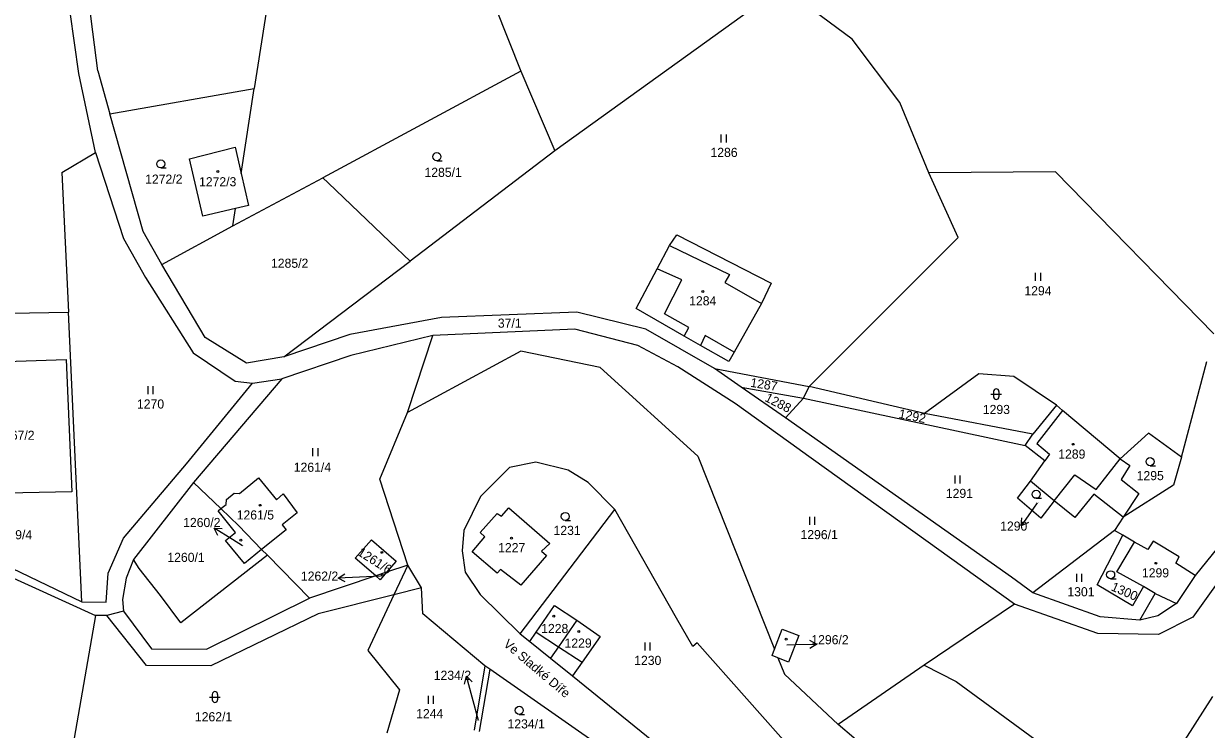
# Model space of a CAD drawing. Extents: x -670359 to -668019, y -978807 to -976674.
# Drawn here: x -670066.9 to -669846.5, y -978074.2 to -977942.9 of the extents above; entities that cross this region are included whole.
import ezdxf

# ---------------------------------------------------------------- set-up
doc = ezdxf.new("R2010")
doc.units = 0
for name, color, linetype in [('Hranice parcel', 7, 'Continuous'), ('Parcelní čísla', 7, 'Continuous'), ('Pop  PČ popisy', 7, 'Continuous'), ('Vnitřní kresba', 7, 'Continuous'), ('Značky budov', 7, 'Continuous'), ('Značky kultur', 7, 'Continuous')]:
    doc.layers.add(name, color=color, linetype=linetype)

msp = doc.modelspace()

# ---------------------------------------------------------------- linework, layer by layer
at = {"layer": 'Hranice parcel'}
for points in [[(-670053.06, -977951.64), (-670057.82, -977914.27)], [(-669986.12, -977921.83), (-669974.21, -977951.73)], [(-670020.22, -977931.15), (-670023.9, -977954.91)], [(-669912.5, -977945.77), (-669928, -977934.27)], [(-670056.57, -977952.14), (-670059, -977934.95)], [(-669929.41, -977938.84), (-669967.89, -977966.56)], [(-669903.64, -977957.54), (-669912.5, -977945.77)], [(-670053.5, -977966.83), (-670056.57, -977952.14)], [(-670053.06, -977951.64), (-670050.8, -977959.63)], [(-669974.21, -977951.73), (-670011.15, -977971.53)], [(-669974.21, -977951.73), (-669967.89, -977966.56)], [(-670050.8, -977959.63), (-670023.9, -977954.91)], [(-670026.36, -977970.75), (-670023.9, -977954.91)], [(-669898.21, -977970.61), (-669903.64, -977957.54)], [(-670044.58, -977981.56), (-670050.8, -977959.63)], [(-670059.75, -977970.54), (-670053.5, -977966.83)], [(-670053.5, -977966.83), (-670048.25, -977982.86)], [(-670035.99, -977968.05), (-670027.48, -977965.87)], [(-670027.48, -977965.87), (-670026.36, -977970.75)], [(-669967.89, -977966.56), (-669994.86, -977987.04)], [(-670033.51, -977978.72), (-670035.99, -977968.05)], [(-670059.75, -977970.54), (-670058.53, -977996.56)], [(-670027.87, -977980.5), (-670011.15, -977971.53)], [(-670026.36, -977970.75), (-670024.98, -977976.72)], [(-670011.15, -977971.53), (-670010.16, -977972.48)], [(-669874.62, -977970.47), (-669898.21, -977970.61)], [(-669892.79, -977982.65), (-669898.21, -977970.61)], [(-669845.11, -978000.59), (-669874.62, -977970.47)], [(-670010.16, -977972.48), (-669998.63, -977983.45)], [(-670027.37, -977977.28), (-670033.51, -977978.72)], [(-670027.87, -977980.5), (-670027.37, -977977.28)], [(-670024.98, -977976.72), (-670027.37, -977977.28)], [(-670041.11, -977987.69), (-670027.87, -977980.5)], [(-670048.25, -977982.86), (-670044.13, -977990.1)], [(-670041.11, -977987.69), (-670044.58, -977981.56)], [(-669946.52, -977984.17), (-669945.17, -977982.16)], [(-669945.17, -977982.16), (-669927.61, -977991.17)], [(-669920.55, -978010.38), (-669892.79, -977982.65)], [(-669998.63, -977983.45), (-669994.86, -977987.04)], [(-669948.82, -977988.5), (-669946.52, -977984.17)], [(-670018.38, -978004.9), (-669994.86, -977987.04)], [(-670033.04, -978001.31), (-670041.11, -977987.69)], [(-669952.75, -977995.9), (-669948.82, -977988.5)], [(-670044.13, -977990.1), (-670035.26, -978004.12)], [(-669927.61, -977991.17), (-669929.43, -977994.93)], [(-669943.79, -978001.01), (-669952.75, -977995.9)], [(-669929.43, -977994.93), (-669934.5, -978004)], [(-670087.67, -977997.06), (-670058.53, -977996.56)], [(-670056, -978050.5), (-670058.53, -977996.56)], [(-669988.99, -977997.53), (-670006.09, -978000.75)], [(-669963.81, -977996.58), (-669988.99, -977997.53)], [(-669950.92, -977999.7), (-669963.81, -977996.58)], [(-670006.09, -978000.75), (-670018.38, -978004.9)], [(-669964.19, -977999.7), (-669990.66, -978000.89)], [(-669952.42, -978002.74), (-669964.19, -977999.7)], [(-669938.16, -978007.05), (-669950.92, -977999.7)], [(-670025.34, -978006.06), (-670033.04, -978001.31)], [(-669990.66, -978000.89), (-670005.91, -978004.66)], [(-669995.38, -978015.23), (-669990.66, -978000.89)], [(-669944.96, -978006.77), (-669952.42, -978002.74)], [(-669940.74, -978002.75), (-669943.79, -978001.01)], [(-669935.48, -978005.76), (-669940.74, -978002.75)], [(-670035.26, -978004.12), (-670027.48, -978009.42)], [(-670018.38, -978004.9), (-670025.34, -978006.06)], [(-670005.91, -978004.66), (-670018.76, -978008.97)], [(-669974.25, -978003.83), (-669995.38, -978015.23)], [(-669959.43, -978006.86), (-669974.25, -978003.83)], [(-669934.5, -978004), (-669935.48, -978005.76)], [(-670083.31, -978006.16), (-670058.93, -978005.38)], [(-670058.93, -978005.38), (-670057.91, -978029.98)], [(-669941.27, -978023.37), (-669959.43, -978006.86)], [(-669934.29, -978013.58), (-669944.96, -978006.77)], [(-669933.18, -978010.54), (-669938.16, -978007.05)], [(-669938.16, -978007.05), (-669920.55, -978010.38)], [(-669851.14, -978023.56), (-669846.46, -978005.72)], [(-670018.76, -978008.97), (-670035.21, -978028.25)], [(-670027.48, -978009.42), (-670024.2, -978009.8)], [(-670024.2, -978009.8), (-670018.76, -978008.97)], [(-669888.89, -978008.04), (-669899.01, -978015.45)], [(-669882.41, -978008.56), (-669888.89, -978008.04)], [(-669874.47, -978013.87), (-669882.41, -978008.56)], [(-670036.51, -978024.82), (-670024.2, -978009.8)], [(-669924.92, -978016.24), (-669933.18, -978010.54)], [(-669933.18, -978010.54), (-669921.58, -978012.55)], [(-669921.58, -978012.55), (-669920.55, -978010.38)], [(-669899.01, -978015.45), (-669920.55, -978010.38)], [(-669922.37, -978022.14), (-669934.29, -978013.58)], [(-669924.92, -978016.24), (-669921.58, -978012.55)], [(-669921.58, -978012.55), (-669880.27, -978021.41)], [(-669874.47, -978013.87), (-669878.84, -978019.25)], [(-669873.34, -978014.9), (-669874.47, -978013.87)], [(-670000.51, -978027.64), (-669995.38, -978015.23)], [(-669878.84, -978019.25), (-669899.01, -978015.45)], [(-669862.58, -978023.86), (-669873.34, -978014.9)], [(-669882.85, -978045.88), (-669924.92, -978016.24)], [(-669880.27, -978021.41), (-669878.84, -978019.25)], [(-669857.33, -978019.12), (-669862.58, -978023.86)], [(-669851.14, -978023.56), (-669857.33, -978019.12)], [(-669922.15, -978022.29), (-669922.37, -978022.14)], [(-669882.27, -978050.91), (-669922.15, -978022.29)], [(-669876.65, -978024.27), (-669880.27, -978021.41)], [(-670048.27, -978038.64), (-670036.51, -978024.82)], [(-669971.42, -978024.51), (-669976.37, -978025.5)], [(-669965.41, -978026), (-669971.42, -978024.51)], [(-669941.27, -978023.37), (-669926.98, -978059.31)], [(-669879.27, -978028.04), (-669876.65, -978024.27)], [(-669862.58, -978023.86), (-669860.81, -978025.13)], [(-669851.14, -978023.56), (-669852.64, -978028.76)], [(-669976.37, -978025.5), (-669981.78, -978030.89)], [(-669961.72, -978028.29), (-669965.41, -978026)], [(-669860.81, -978025.13), (-669862.4, -978027.7)], [(-670035.21, -978028.25), (-670046.41, -978042.62)], [(-670030.13, -978033.12), (-670035.21, -978028.25)], [(-670030.13, -978033.12), (-670029.16, -978032.34), (-670029.07, -978031.43), (-670027.62, -978030.26), (-670026.64, -978030.3), (-670023.09, -978027.43), (-670019.78, -978031.52), (-670018.53, -978030.41), (-670015.91, -978033.93), (-670018.67, -978036.17), (-670017.94, -978037.06), (-670022.54, -978040.77)], [(-669995.3, -978043.67), (-670000.51, -978027.64)], [(-669956.73, -978033.3), (-669961.72, -978028.29)], [(-669881.73, -978031.17), (-669879.27, -978028.04)], [(-669874.85, -978031.69), (-669879.27, -978028.04)], [(-669862.4, -978027.7), (-669859.11, -978030.32)], [(-669852.64, -978028.76), (-669862.04, -978034.73)], [(-670057.91, -978029.98), (-670082.22, -978030.53)], [(-669981.78, -978030.89), (-669984.86, -978037.22)], [(-669877.39, -978034.9), (-669881.73, -978031.17)], [(-669867.5, -978030.45), (-669871, -978034.78)], [(-669862.04, -978034.73), (-669867.5, -978030.45)], [(-669859.11, -978030.32), (-669862.04, -978034.73)], [(-669837.27, -978031.54), (-669848.63, -978045.6)], [(-670022.54, -978040.77), (-670025.74, -978043.36), (-670029.23, -978039.04), (-670027.4, -978037.57), (-670030.65, -978033.55), (-670030.13, -978033.12)], [(-670026.77, -978036.35), (-670030.13, -978033.12)], [(-669977.84, -978034.54), (-669976.49, -978033.01)], [(-669976.49, -978033.01), (-669968.85, -978039.6)], [(-669974.36, -978056.42), (-669956.73, -978033.3)], [(-669945.24, -978053.55), (-669956.73, -978033.3)], [(-669874.85, -978031.69), (-669877.39, -978034.9)], [(-669871, -978034.78), (-669874.85, -978031.69)], [(-669834.38, -978032.89), (-669849.06, -978053.35)], [(-669981.82, -978037.6), (-669978.64, -978034.07)], [(-669978.64, -978034.07), (-669977.84, -978034.54)], [(-669862.04, -978034.73), (-669863.64, -978037.18)], [(-670083.87, -978037.17), (-670056, -978050.5)], [(-670022.54, -978040.77), (-670026.77, -978036.35)], [(-669984.86, -978037.22), (-669985.16, -978040.98)], [(-669980.94, -978038.39), (-669981.82, -978037.6)], [(-669863.64, -978037.18), (-669878.84, -978048.81)], [(-669866.85, -978047.3), (-669862.1, -978038.09)], [(-669862.1, -978038.09), (-669863.64, -978037.18)], [(-669859.94, -978039.35), (-669862.1, -978038.09)], [(-670083.53, -978039.41), (-670053.47, -978053.05)], [(-670051.11, -978045.13), (-670048.27, -978038.64)], [(-670005.07, -978042.39), (-670002.08, -978038.94)], [(-670002.08, -978038.94), (-669997.46, -978042.91)], [(-669983.32, -978041.21), (-669980.94, -978038.39)], [(-669968.85, -978039.6), (-669970.37, -978041.05)], [(-669863.19, -978044.88), (-669859.94, -978039.35)], [(-669857.45, -978040.77), (-669859.94, -978039.35)], [(-669856.42, -978039.17), (-669857.45, -978040.77)], [(-669851.6, -978042.1), (-669856.42, -978039.17)], [(-670046.41, -978042.62), (-670047.75, -978046.07)], [(-670045.36, -978044.29), (-670046.41, -978042.62)], [(-670021.46, -978041.83), (-670037.55, -978054.4)], [(-670021.46, -978041.83), (-670022.54, -978040.77)], [(-670013.58, -978049.78), (-670021.46, -978041.83)], [(-670001.27, -978045.67), (-670005.07, -978042.39)], [(-669985.16, -978040.98), (-669984.58, -978044.97)], [(-669978.66, -978045.17), (-669983.32, -978041.21)], [(-669969.48, -978041.84), (-669974.25, -978047.39)], [(-669970.37, -978041.05), (-669969.48, -978041.84)], [(-669852.24, -978043.3), (-669851.6, -978042.1)], [(-670041.34, -978049.3), (-670045.36, -978044.29)], [(-669997.46, -978042.91), (-669999.26, -978044.99)], [(-669995.3, -978043.67), (-669999.26, -978044.99)], [(-669995.3, -978043.67), (-669997.88, -978049.19)], [(-669992.72, -978047.89), (-669995.3, -978043.67)], [(-669978.03, -978044.45), (-669978.66, -978045.17)], [(-669974.25, -978047.39), (-669978.03, -978044.45)], [(-669848.63, -978045.6), (-669852.24, -978043.3)], [(-670051.49, -978050.56), (-670051.11, -978045.13)], [(-670047.75, -978046.07), (-670048.45, -978050.07)], [(-670001.27, -978045.67), (-670013.58, -978049.78)], [(-669999.26, -978044.99), (-670001.27, -978045.67)], [(-670000.45, -978046.37), (-670001.27, -978045.67)], [(-669999.26, -978044.99), (-670000.45, -978046.37)], [(-669984.58, -978044.97), (-669981.84, -978049.11)], [(-669878.84, -978048.81), (-669882.85, -978045.88)], [(-669858.21, -978047.65), (-669863.19, -978044.88)], [(-669848.63, -978045.6), (-669852.12, -978050.81)], [(-669997.88, -978049.19), (-670002.72, -978059.52)], [(-669992.48, -978052.73), (-669992.72, -978047.89)], [(-669981.84, -978049.11), (-669974.36, -978056.42)], [(-669866.34, -978053.29), (-669878.84, -978048.81)], [(-669860.27, -978051.26), (-669866.85, -978047.3)], [(-669858.21, -978047.65), (-669860.27, -978051.26)], [(-669858.9, -978053.89), (-669856.05, -978048.92)], [(-669856.05, -978048.92), (-669858.21, -978047.65)], [(-670056, -978050.5), (-670051.49, -978050.56)], [(-670048.45, -978050.07), (-670048.28, -978052.22)], [(-670037.55, -978054.4), (-670041.34, -978049.3)], [(-669971.4, -978056.16), (-669967.99, -978051.18)], [(-669967.99, -978051.18), (-669963.82, -978053.88)], [(-669882.27, -978050.91), (-669899.08, -978062.28)], [(-669866.72, -978056.41), (-669882.27, -978050.91)], [(-669852.12, -978050.81), (-669855.54, -978053.07)], [(-670053.47, -978053.05), (-670058.45, -978081.6)], [(-670051.39, -978053.04), (-670053.47, -978053.05)], [(-670048.28, -978052.22), (-670051.39, -978053.04)], [(-669980.96, -978062.4), (-669992.48, -978052.73)], [(-669942.19, -978058.82), (-669945.24, -978053.55)], [(-669858.9, -978053.89), (-669866.34, -978053.29)], [(-669855.54, -978053.07), (-669858.9, -978053.89)], [(-669849.06, -978053.35), (-669855.44, -978056.59)], [(-669963.82, -978053.88), (-669967.23, -978058.85)], [(-669963.82, -978053.88), (-669959.48, -978056.97)], [(-669926.98, -978059.31), (-669925.55, -978055.57)], [(-669925.55, -978055.57), (-669922.46, -978056.76)], [(-669974.36, -978056.42), (-669972.57, -978057.86)], [(-669972.57, -978057.86), (-669971.4, -978056.16)], [(-669972.57, -978057.86), (-669968.7, -978060.99)], [(-669959.48, -978056.97), (-669962.82, -978061.7)], [(-669922.46, -978056.76), (-669924.36, -978061.71)], [(-669855.44, -978056.59), (-669866.72, -978056.41)], [(-670002.72, -978059.52), (-669996.86, -978066.86)], [(-669967.23, -978058.85), (-669968.7, -978060.99)], [(-669941.37, -978058.13), (-669942.19, -978058.82)], [(-669932.15, -978068.55), (-669941.37, -978058.13)], [(-669927.43, -978060.47), (-669926.98, -978059.31)], [(-669980.96, -978062.4), (-669982.91, -978074.36)], [(-669980.03, -978063.05), (-669980.96, -978062.4)], [(-669968.7, -978060.99), (-669964.64, -978064.28)], [(-669962.82, -978061.7), (-669964.64, -978064.28)], [(-669926.35, -978060.91), (-669927.43, -978060.47)], [(-669926.35, -978060.91), (-669925.14, -978063.95)], [(-669924.36, -978061.71), (-669926.35, -978060.91)], [(-669899.08, -978062.28), (-669915.09, -978073.32)], [(-669899.08, -978062.28), (-669893.12, -978065.33)], [(-669980.03, -978063.05), (-669981.98, -978074.61)], [(-669951.97, -978082.63), (-669980.03, -978063.05)], [(-669964.64, -978064.28), (-669935.73, -978087.67)], [(-669915.09, -978073.32), (-669925.14, -978063.95)], [(-669996.86, -978066.86), (-669999.21, -978074.92)], [(-669893.12, -978065.33), (-669864.05, -978086.6)], [(-669922.9, -978078.96), (-669932.15, -978068.55)], [(-669845.36, -978068.08), (-669851.96, -978078.41)], [(-669903.47, -978083.25), (-669915.09, -978073.32)]]:
    msp.add_lwpolyline(points, dxfattribs=at)
at = {"layer": 'Parcelní čísla'}
for p, q in [((-669878.05, -978032.08), (-669878.75, -978033.08)), ((-669879.68, -978035.72), (-669881.04, -978036.36)), ((-670030.66, -978038.11), (-670031.37, -978036.79)), ((-670026.07, -978040.08), (-670027.97, -978038.9)), ((-670006.94, -978046.78), (-670008.28, -978046.1)), ((-670000.44, -978045.71), (-670004.28, -978045.9)), ((-669920.44, -978057.65), (-669919.12, -978058.37)), ((-669924.7, -978058.48), (-669923.12, -978058.45)), ((-669984.76, -978065.8), (-669984.38, -978064.35)), ((-669982.15, -978072.58), (-669983.33, -978068.21))]:
    msp.add_line(p, q, dxfattribs=at)
for points in [[(-669878.75, -978033.08), (-669881.04, -978036.36), (-669880.91, -978034.87)], [(-670027.97, -978038.9), (-670031.37, -978036.79), (-670029.87, -978036.84)], [(-670004.28, -978045.9), (-670008.28, -978046.1), (-670007.01, -978045.28)], [(-669923.12, -978058.45), (-669919.12, -978058.37), (-669920.41, -978059.15)], [(-669983.33, -978068.21), (-669984.38, -978064.35), (-669983.31, -978065.41)]]:
    msp.add_lwpolyline(points, dxfattribs=at)
at = {"layer": 'Vnitřní kresba'}
for points in [[(-669946.52, -977984.17), (-669935.38, -977989.54)], [(-669944.25, -977990.55), (-669948.82, -977988.5)], [(-669935.38, -977989.54), (-669936.25, -977991.06)], [(-669947.49, -977996.88), (-669944.25, -977990.55)], [(-669936.25, -977991.06), (-669929.43, -977994.93)], [(-669942.92, -977999.41), (-669947.49, -977996.88)], [(-669943.79, -978001.01), (-669942.92, -977999.41)], [(-669939.87, -978000.91), (-669940.74, -978002.75)], [(-669934.5, -978004), (-669939.87, -978000.91)], [(-669873.34, -978014.9), (-669878.11, -978021)], [(-669878.11, -978021), (-669875.78, -978022.98)], [(-669875.78, -978022.98), (-669876.65, -978024.27)], [(-669867.03, -978029.56), (-669862.58, -978023.86)], [(-669874.85, -978031.69), (-669871.04, -978026.87)], [(-669871.04, -978026.87), (-669867.03, -978029.56)], [(-669997.88, -978049.19), (-670011.97, -978052.72)], [(-669992.72, -978047.89), (-669997.88, -978049.19)], [(-669856.05, -978048.92), (-669852.12, -978050.81)], [(-670032.8, -978059.32), (-670013.58, -978049.78)], [(-670043.98, -978062.35), (-670051.39, -978053.04)], [(-670048.28, -978052.22), (-670043.04, -978059.22)], [(-670011.97, -978052.72), (-670031.99, -978062.43)], [(-669971.4, -978056.16), (-669967.23, -978058.85)], [(-670043.04, -978059.22), (-670032.8, -978059.32)], [(-669967.23, -978058.85), (-669962.82, -978061.7)], [(-670031.99, -978062.43), (-670043.98, -978062.35)]]:
    msp.add_lwpolyline(points, dxfattribs=at)
at = {"layer": 'Značky budov'}
for centre in [(-670030.68, -977970.37), (-669940.34, -977992.7), (-669871.34, -978021.16), (-670022.8, -978032.52), (-669975.97, -978038.65), (-669855.91, -978043.31), (-670000.05, -978045.52), (-669968.12, -978053.16), (-669963.46, -978056.02), (-669924.79, -978057.42)]:
    msp.add_circle(centre, 0.175, dxfattribs=at)
at = {"layer": 'Značky kultur'}
for p, q in [((-669936.95, -977963.47), (-669936.95, -977964.97)), ((-669935.95, -977964.97), (-669935.95, -977963.47)), ((-670041.31, -977969.72), (-670040.31, -977969.72)), ((-669989.88, -977968.37), (-669988.88, -977968.37)), ((-669878.39, -977989.23), (-669878.39, -977990.73)), ((-669877.39, -977990.73), (-669877.39, -977989.23)), ((-670043.75, -978010.31), (-670043.75, -978011.81)), ((-670042.75, -978011.81), (-670042.75, -978010.31)), ((-669886.17, -978011.33), (-669886.17, -978012.33)), ((-669885.17, -978011.33), (-669885.17, -978012.33)), ((-669886.67, -978011.83), (-669884.67, -978011.83)), ((-670013.02, -978021.89), (-670013.02, -978023.39)), ((-670012.02, -978023.39), (-670012.02, -978021.89)), ((-669893.38, -978026.95), (-669893.38, -978028.45)), ((-669892.38, -978028.45), (-669892.38, -978026.95)), ((-669857.01, -978025.14), (-669856.01, -978025.14)), ((-669878.24, -978031.22), (-669877.24, -978031.22)), ((-669965.97, -978035.34), (-669964.97, -978035.34)), ((-669920.48, -978034.66), (-669920.48, -978036.16)), ((-669919.48, -978036.16), (-669919.48, -978034.66)), ((-669870.74, -978045.26), (-669870.74, -978046.76)), ((-669869.74, -978046.76), (-669869.74, -978045.26)), ((-669864.36, -978046.19), (-669863.36, -978046.19)), ((-669951.12, -978058.04), (-669951.12, -978059.54)), ((-669950.12, -978059.54), (-669950.12, -978058.04)), ((-670032.23, -978068.21), (-670030.23, -978068.21)), ((-670031.73, -978067.71), (-670031.73, -978068.71)), ((-670030.73, -978067.71), (-670030.73, -978068.71)), ((-669991.52, -978068), (-669991.52, -978069.5)), ((-669990.52, -978069.5), (-669990.52, -978068)), ((-669974.53, -978071.44), (-669973.53, -978071.44))]:
    msp.add_line(p, q, dxfattribs=at)
for centre, radius in [((-669989.88, -977967.62), 0.75), ((-670041.31, -977968.97), 0.75), ((-670030.68, -977970.37), 0.175), ((-669940.34, -977992.7), 0.175), ((-669871.34, -978021.16), 0.175), ((-669857.01, -978024.39), 0.75), ((-669878.24, -978030.47), 0.75), ((-670022.8, -978032.52), 0.175), ((-669965.97, -978034.59), 0.75), ((-670026.4, -978039.02), 0.175), ((-669975.97, -978038.65), 0.175), ((-670000.11, -978041.28), 0.175), ((-669864.36, -978045.44), 0.75), ((-669855.91, -978043.31), 0.175), ((-670000.05, -978045.52), 0.175), ((-669968.12, -978053.16), 0.175), ((-669963.46, -978056.02), 0.175), ((-669924.79, -978057.42), 0.175), ((-669974.53, -978070.69), 0.75)]:
    msp.add_circle(centre, radius, dxfattribs=at)
for centre, start, end in [((-669885.67, -978011.33), 0, 180), ((-669885.67, -978012.33), 180, 0), ((-670031.23, -978067.71), 0, 180), ((-670031.23, -978068.71), 180, 0)]:
    msp.add_arc(centre, 0.5, start, end, dxfattribs=at)

# ---------------------------------------------------------------- texts
at = {"layer": 'Parcelní čísla'}
for s, height, p in [('1286', 1.7, (-669938.91, -977967.67)), ('1285/1', 1.7, (-669992.19, -977971.38)), ('1272/2', 1.7, (-670044.23, -977972.65)), ('1272/3', 1.7, (-670034.19, -977973.14)), ('1285/2', 1.7, (-670020.78, -977988.3)), ('1294', 1.7, (-669880.43, -977993.43)), ('1284', 1.7, (-669942.88, -977995.3)), ('37/1', 1.7, (-669978.52, -977999.46)), ('1270', 1.7, (-670045.75, -978014.51)), ('1293', 1.7, (-669888.17, -978015.53)), ('1267/2', 1.7, (-670071.78, -978020.33)), ('1289', 1.7, (-669874.12, -978023.83)), ('1261/4', 1.7, (-670016.54, -978026.28)), ('1295', 1.7, (-669859.51, -978027.84)), ('1291', 1.7, (-669895.06, -978031.15)), ('1261/5', 1.7, (-670027.17, -978035.16)), ('1290', 0.1, (-669878.05, -978032.08)), ('1260/2', 1.7, (-670037.15, -978036.57)), ('1290', 1.7, (-669884.94, -978037.24)), ('1269/4', 1.7, (-670072.23, -978038.85)), ('1231', 1.7, (-669968.15, -978038.04)), ('1296/1', 1.7, (-669922.14, -978038.82)), ('1260/2', 0.1, (-670026.31, -978040.08)), ('1227', 1.7, (-669978.47, -978041.25)), ('1260/1', 1.7, (-670040.09, -978043.06)), ('1262/2', 1.7, (-670015.21, -978046.55)), ('1299', 1.7, (-669858.53, -978045.94)), ('1262/2', 0.1, (-670000.68, -978045.71)), ('1301', 1.7, (-669872.42, -978049.46)), ('1228', 1.7, (-669970.45, -978056.3)), ('1229', 1.7, (-669966.1, -978059.02)), ('1296/2', 1.7, (-669920.12, -978058.39)), ('1296/2', 0.1, (-669924.7, -978058.48)), ('1230', 1.7, (-669953.12, -978062.24)), ('1234/2', 1.7, (-669990.46, -978065.01)), ('1262/1', 1.7, (-670034.96, -978072.73)), ('1244', 1.7, (-669993.74, -978072.15)), ('1234/2', 0.1, (-669982.39, -978072.58)), ('1234/1', 1.7, (-669976.72, -978074.06))]:
    msp.add_text(s, height=height, dxfattribs=at).set_placement(p)
for s, rotation, p in [('1287', 350.9747, (-669931.56, -978010.45)), ('1288', 332.796, (-669928.93, -978013.04)), ('1292', 348.918, (-669903.94, -978016.25)), ('1261/6', 327.5321, (-670004.81, -978041.67)), ('1300', 336.413, (-669864.42, -978048.3))]:
    msp.add_text(s, height=1.7, rotation=rotation, dxfattribs=at).set_placement(p)
at = {"layer": 'Pop  PČ popisy'}
msp.add_text('Ve Sladké Díře', height=1.7, rotation=319.6957, dxfattribs=at).set_placement((-669977.6, -978058.59))

doc.saveas('drawing.dxf')
